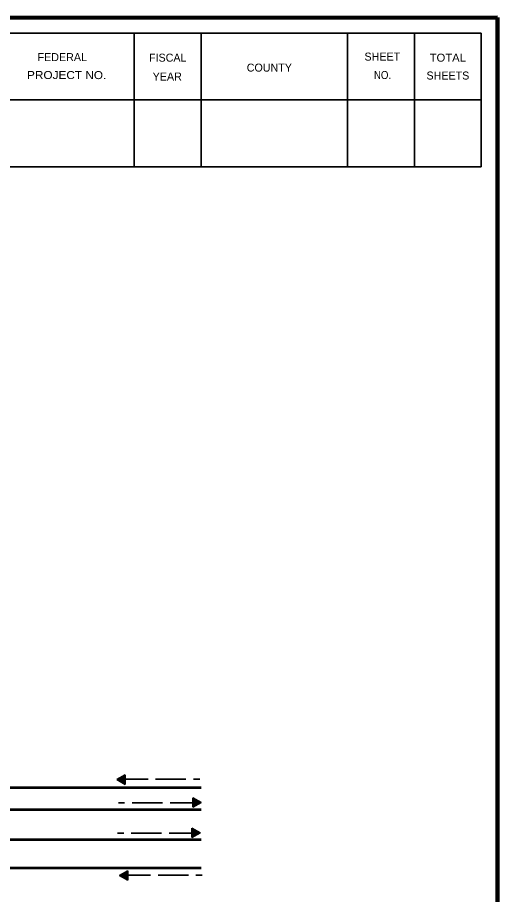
# Model space of a CAD drawing. Extents: x -90 to 623, y -379 to 75.
# Drawn here: x 541.1 to 617.2, y -69.7 to 69.4 of the extents above; entities that cross this region are included whole.
import ezdxf

# ---------------------------------------------------------------- set-up
doc = ezdxf.new("R2010")
doc.units = 0
doc.header["$LTSCALE"] = 0.8
doc.linetypes.add('LONG_DASHED', pattern=[7.5, 6, -1.5])
doc.layers.add('1', color=7, linetype='Continuous', lineweight=35)
doc.layers.add('61', color=7, linetype='Continuous', lineweight=35)

msp = doc.modelspace()

# ---------------------------------------------------------------- linework, layer by layer
at = {"layer": '1', "lineweight": 158}
msp.add_line((617.1938, -368.9978), (617.1938, 69.4188), dxfattribs=at)
at = {"layer": '1', "lineweight": 13}
msp.add_line((617.1938, -368.9978), (617.1938, 69.4188), dxfattribs=at)
at = {"layer": '1'}
for p, q in [((558.1721, -50.7385), (556.8639, -51.4939)), ((556.915, -51.5046), (556.915, -51.4614)), ((556.9456, -51.5217), (556.9456, -51.444)), ((556.9711, -51.5359), (556.9711, -51.4296)), ((556.9909, -51.5471), (556.9908, -51.4184)), ((557.0132, -51.5596), (557.0132, -51.4057)), ((557.0269, -51.5674), (557.0268, -51.398)), ((557.0556, -51.5834), (557.0556, -51.3817)), ((557.1008, -51.6089), (557.1008, -51.3562)), ((557.1323, -51.6265), (557.1322, -51.3383)), ((557.1798, -51.6532), (557.1798, -51.3114)), ((557.2252, -51.6787), (557.2251, -51.2857)), ((557.254, -51.6948), (557.254, -51.2693)), ((557.2802, -51.7096), (557.2802, -51.2546)), ((557.3108, -51.7268), (557.311, -51.2372)), ((557.3392, -51.7428), (557.3393, -51.221)), ((557.3731, -51.7617), (557.3731, -51.202)), ((557.4037, -51.779), (557.4037, -51.1846)), ((557.4312, -51.7945), (557.4312, -51.1689)), ((557.4726, -51.8177), (557.4726, -51.1456)), ((557.4939, -51.8296), (557.494, -51.1333)), ((557.5322, -51.8511), (557.5322, -51.1118)), ((557.5675, -51.8708), (557.5672, -51.0918)), ((557.6078, -51.8937), (557.6078, -51.0689)), ((557.6461, -51.9151), (557.6462, -51.0472)), ((557.6735, -51.9305), (557.6734, -51.0317)), ((557.7005, -51.9457), (557.7005, -51.0163)), ((557.7273, -51.9606), (557.7273, -51.0013)), ((557.7441, -51.97), (557.7441, -50.9917)), ((557.7663, -51.9826), (557.7663, -50.979)), ((557.7898, -51.9958), (557.7899, -50.9659)), ((557.8175, -52.0113), (557.8176, -50.9501)), ((557.8482, -52.0287), (557.8483, -50.9328)), ((557.8726, -52.0423), (557.8726, -50.919)), ((557.8971, -52.0561), (557.8971, -50.9051)), ((557.9055, -52.0607), (557.9056, -50.9003)), ((557.9422, -52.0815), (557.9424, -50.8794)), ((557.9652, -52.0943), (557.9652, -50.8665)), ((557.9791, -52.1021), (557.9792, -50.8587)), ((558.0013, -52.1145), (558.0013, -50.8461)), ((558.0364, -52.1343), (558.0364, -50.8262)), ((558.0632, -52.1493), (558.0632, -50.8109)), ((558.0952, -52.1674), (558.0952, -50.7928)), ((558.1089, -52.1749), (558.109, -50.7851)), ((558.1286, -52.1779), (558.1286, -50.788)), ((558.1503, -52.1983), (558.1503, -50.7616)), ((558.162, -52.2237), (558.1619, -50.7624)), ((558.1722, -52.2492), (558.1721, -50.7385)), ((558.1722, -52.2492), (556.8639, -51.4939)), ((568.9053, -54.3872), (570.2136, -55.1424)), ((568.9053, -54.3872), (568.9054, -55.8978)), ((568.9054, -55.8978), (570.2136, -55.1424)), ((568.9155, -54.4127), (568.9156, -55.8739)), ((568.9272, -54.4381), (568.9272, -55.8747)), ((568.9489, -54.4584), (568.9489, -55.8483)), ((568.9686, -54.4614), (568.9685, -55.8513)), ((568.9823, -54.4689), (568.9823, -55.8435)), ((569.0143, -54.487), (569.0142, -55.8254)), ((569.0411, -54.5021), (569.0411, -55.8102)), ((569.0762, -54.5218), (569.0762, -55.7903)), ((569.0984, -54.5343), (569.0983, -55.7777)), ((569.1123, -54.542), (569.1123, -55.7698)), ((569.1352, -54.5548), (569.1351, -55.7569)), ((569.172, -54.5757), (569.1719, -55.736)), ((569.1804, -54.5802), (569.1804, -55.7312)), ((569.2049, -54.594), (569.2049, -55.7173)), ((569.2293, -54.6077), (569.2292, -55.7035)), ((569.26, -54.625), (569.2599, -55.6863)), ((569.2877, -54.6406), (569.2876, -55.6704)), ((569.3112, -54.6537), (569.3112, -55.6573)), ((569.3334, -54.6663), (569.3334, -55.6446)), ((569.3502, -54.6758), (569.3502, -55.635)), ((569.377, -54.6907), (569.377, -55.62)), ((569.404, -54.7058), (569.4041, -55.6046)), ((569.4314, -54.7212), (569.4313, -55.5891)), ((569.4697, -54.7426), (569.4697, -55.5674)), ((569.51, -54.7655), (569.5102, -55.5445)), ((569.5453, -54.7852), (569.5453, -55.5245)), ((569.5836, -54.8068), (569.5835, -55.503)), ((569.6049, -54.8187), (569.6049, -55.4907)), ((569.6463, -54.8418), (569.6463, -55.4674)), ((569.6738, -54.8573), (569.6738, -55.4517)), ((569.7044, -54.8746), (569.7044, -55.4343)), ((569.7382, -54.8936), (569.7382, -55.4153)), ((569.7667, -54.9095), (569.7665, -55.3992)), ((569.7973, -54.9267), (569.7973, -55.3817)), ((569.8235, -54.9415), (569.8235, -55.367)), ((569.8523, -54.9577), (569.8524, -55.3507)), ((569.8977, -54.9831), (569.8977, -55.3249)), ((569.9452, -55.0098), (569.9452, -55.298)), ((569.9767, -55.0274), (569.9767, -55.2802)), ((570.0219, -55.0529), (570.0219, -55.2546)), ((570.0506, -55.0689), (570.0507, -55.2383)), ((570.0643, -55.0767), (570.0643, -55.2306)), ((570.0866, -55.0892), (570.0867, -55.2179)), ((570.1064, -55.1004), (570.1064, -55.2067)), ((570.1319, -55.1146), (570.1319, -55.1923)), ((570.1625, -55.1317), (570.1625, -55.1749)), ((568.757, -59.1793), (570.0653, -59.9346)), ((568.757, -59.1793), (568.7572, -60.69)), ((568.7672, -59.2048), (568.7673, -60.6661)), ((568.7789, -59.2302), (568.7789, -60.6669)), ((568.8007, -59.2506), (568.8007, -60.6405)), ((568.8203, -59.2536), (568.8202, -60.6434)), ((568.8341, -59.2611), (568.834, -60.6357)), ((568.8661, -59.2792), (568.866, -60.6176)), ((568.8928, -59.2942), (568.8928, -60.6023)), ((568.928, -59.314), (568.928, -60.5824)), ((568.9502, -59.3264), (568.9501, -60.5698)), ((568.964, -59.3342), (568.964, -60.562)), ((568.987, -59.347), (568.9868, -60.5491)), ((569.0237, -59.3678), (569.0237, -60.5282)), ((569.0322, -59.3724), (569.0322, -60.5234)), ((569.0567, -59.3862), (569.0567, -60.5095)), ((569.0811, -59.3998), (569.081, -60.4957)), ((569.1118, -59.4172), (569.1117, -60.4784)), ((569.1395, -59.4327), (569.1393, -60.4626)), ((569.1629, -59.4459), (569.163, -60.4495)), ((569.1852, -59.4585), (569.1852, -60.4367)), ((569.202, -59.4679), (569.202, -60.4272)), ((569.2287, -59.4828), (569.2287, -60.4122)), ((569.2558, -59.498), (569.2558, -60.3967)), ((569.2832, -59.5134), (569.2831, -60.3813)), ((569.3214, -59.5347), (569.3214, -60.3596)), ((569.3618, -59.5577), (569.362, -60.3367)), ((569.397, -59.5774), (569.397, -60.3167)), ((569.4353, -59.5989), (569.4352, -60.2952)), ((569.4567, -59.6108), (569.4567, -60.2829)), ((569.498, -59.634), (569.498, -60.2596)), ((569.5256, -59.6495), (569.5256, -60.2439)), ((569.5562, -59.6668), (569.5562, -60.2265)), ((569.59, -59.6857), (569.5899, -60.2075)), ((569.6184, -59.7017), (569.6182, -60.1913)), ((569.6491, -59.7189), (569.6491, -60.1739)), ((569.6753, -59.7337), (569.6753, -60.1592)), ((569.7041, -59.7498), (569.7042, -60.1428)), ((569.7495, -59.7752), (569.7494, -60.1171)), ((569.7969, -59.802), (569.797, -60.0902)), ((569.8284, -59.8196), (569.8284, -60.0723)), ((568.7572, -60.69), (570.0653, -59.9346)), ((569.8737, -59.8451), (569.8737, -60.0467)), ((569.9023, -59.8611), (569.9024, -60.0305)), ((569.9161, -59.8689), (569.9161, -60.0227)), ((569.9383, -59.8814), (569.9384, -60.0101)), ((569.9582, -59.8926), (569.9582, -59.9989)), ((569.9837, -59.9067), (569.9837, -59.9845)), ((570.0142, -59.9239), (570.0142, -59.9671)), ((558.5672, -65.9547), (557.2591, -66.7101)), ((558.5674, -67.4653), (557.2591, -66.7101)), ((557.3102, -66.7207), (557.3102, -66.6776)), ((557.3407, -66.7379), (557.3407, -66.6602)), ((557.3663, -66.7521), (557.3663, -66.6457)), ((557.3861, -66.7632), (557.386, -66.6346)), ((557.4083, -66.7758), (557.4083, -66.6219)), ((557.4221, -66.7836), (557.422, -66.6142)), ((557.4507, -66.7996), (557.4507, -66.5979)), ((557.496, -66.8251), (557.496, -66.5723)), ((557.5275, -66.8427), (557.5274, -66.5545)), ((557.5749, -66.8694), (557.575, -66.5276)), ((557.6203, -66.8948), (557.6202, -66.5018)), ((557.6492, -66.911), (557.6492, -66.4855)), ((557.6753, -66.9257), (557.6753, -66.4707)), ((557.706, -66.943), (557.7062, -66.4533)), ((557.7344, -66.9589), (557.7345, -66.4372)), ((557.7682, -66.9779), (557.7682, -66.4182)), ((557.7988, -66.9952), (557.7988, -66.4008)), ((557.8264, -67.0107), (557.8264, -66.3851)), ((557.8678, -67.0338), (557.8678, -66.3618)), ((557.8891, -67.0457), (557.8892, -66.3495)), ((557.9274, -67.0673), (557.9274, -66.328)), ((557.9627, -67.087), (557.9624, -66.308)), ((558.003, -67.1099), (558.003, -66.2851)), ((558.0412, -67.1312), (558.0413, -66.2634)), ((558.0687, -67.1467), (558.0686, -66.2479)), ((558.0957, -67.1618), (558.0957, -66.2325)), ((558.1224, -67.1767), (558.1224, -66.2175)), ((558.1392, -67.1862), (558.1392, -66.2079)), ((558.1615, -67.1988), (558.1614, -66.1952)), ((558.1849, -67.2119), (558.1851, -66.1821)), ((558.2127, -67.2275), (558.2128, -66.1662)), ((558.2433, -67.2448), (558.2434, -66.149)), ((558.2677, -67.2585), (558.2677, -66.1352)), ((558.2922, -67.2722), (558.2922, -66.1213)), ((558.3007, -67.2768), (558.3007, -66.1165)), ((558.3374, -67.2977), (558.3376, -66.0956)), ((558.3604, -67.3105), (558.3604, -66.0827)), ((558.3742, -67.3182), (558.3743, -66.0748)), ((558.3964, -67.3307), (558.3964, -66.0622)), ((558.4316, -67.3504), (558.4316, -66.0423)), ((558.4583, -67.3655), (558.4584, -66.0271)), ((558.4903, -67.3836), (558.4904, -66.009)), ((558.5041, -67.3911), (558.5042, -66.0012)), ((558.5237, -67.3941), (558.5237, -66.0042)), ((558.5455, -67.4144), (558.5455, -65.9778)), ((558.5572, -67.4398), (558.5571, -65.9786)), ((558.5674, -67.4653), (558.5672, -65.9547))]:
    msp.add_line(p, q, dxfattribs=at)
at = {"layer": '1', "linetype": 'LONG_DASHED'}
for p, q in [((556.9931, -51.4437), (569.9931, -51.4437)), ((570.0844, -55.1927), (557.0844, -55.1927)), ((569.9362, -59.9848), (556.9362, -59.9848)), ((557.3882, -66.6598), (570.3882, -66.6598))]:
    msp.add_line(p, q, dxfattribs=at)
at = {"layer": '1', "lineweight": 53}
msp.add_line((517.2255, -61.0037), (570.2255, -61.0037), dxfattribs=at)
at = {"layer": '1', "lineweight": 158}
msp.add_lwpolyline([(617.1938, 69.4188), (-42.5562, 69.3355), (-42.4728, -368.9978)], dxfattribs=at)
at = {"layer": '1', "lineweight": 53}
for points in [[(501.7255, 21.7462), (501.7255, -11.7538), (517.7255, -11.7538), (517.7255, 16.2462), (496.7255, 16.2462), (496.7255, -7.7538), (512.7255, -7.7538), (512.7255, 12.7462), (491.7255, 12.7462), (491.7255, -16.2538), (526.7255, -16.2538), (526.7255, -56.2537), (570.2255, -56.2537)], [(531.7255, 21.7462), (531.7255, -52.7537), (570.2255, -52.7537)], [(517.2255, -61.0037), (517.2255, -27.5038), (496.2255, -27.5038), (496.2255, -61.0037), (512.2255, -61.0037), (512.2255, -32.0037), (491.2255, -32.0037), (491.2255, -56.5037), (507.7255, -56.5037), (507.7255, -36.5037), (486.7255, -36.5037), (486.7255, -65.5037), (570.2255, -65.5037)]]:
    msp.add_lwpolyline(points, dxfattribs=at)
at = {"layer": '61'}
for p, q in [((559.6105, 66.9188), (559.6105, 45.7522)), ((570.1938, 66.9188), (570.1938, 45.7522)), ((593.4438, 66.9188), (593.4438, 45.7522)), ((604.0272, 66.9188), (604.0272, 45.7522)), ((614.6105, 56.3355), (500.3605, 56.3355))]:
    msp.add_line(p, q, dxfattribs=at)
for points in [[(614.6105, 66.9188), (500.3605, 66.9188), (500.3605, 45.7522)], [(614.6105, 66.9188), (614.6105, 45.7522), (500.3605, 45.7522)]]:
    msp.add_lwpolyline(points, dxfattribs=at)

# ---------------------------------------------------------------- texts
for s, height, rotation, p in [('FEDERAL', 1.27, 0.007, (544.2772, 62.5022)), ('FISCAL', 1.271, 359.942, (561.9438, 62.4188)), ('SHEET', 1.271, 0.059, (596.1105, 62.5855)), ('COUNTY', 1.269, 0.069, (577.4438, 60.8355)), ('YEAR', 1.27, 0.105, (562.5272, 59.4188)), ('SHEETS', 1.269, 359.959, (605.9438, 59.5855))]:
    msp.add_text(s, height=height, rotation=rotation, dxfattribs=at).set_placement(p)
for s, rotation, width, p in [('TOTAL', 359.926, 1.05, (606.4438, 62.4188)), ('PROJECT NO.', 359.922, 1.1, (542.6105, 59.6688)), ('NO.', 359.852, 0.9, (597.6105, 59.6688))]:
    msp.add_text(s, height=1.27, rotation=rotation, dxfattribs=dict(at, width=width)).set_placement(p)

doc.saveas('drawing.dxf')
